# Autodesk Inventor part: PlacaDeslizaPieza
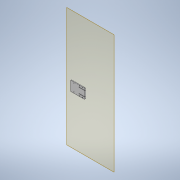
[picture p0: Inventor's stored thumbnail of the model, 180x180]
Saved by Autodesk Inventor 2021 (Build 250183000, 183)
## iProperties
Created: 2021-02
Part Number: PlacaDeslizaPieza
Material: Genérico
Document SubType Name: Modeling
Designer: ATOUZA
Density: 1 g/cm^3
Appearance: Valor por defecto
Author: ATOUZA
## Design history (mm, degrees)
node "Plano de trabajo1"
sketch "Boceto1"
  geometry: L1 (16.874, 259.805)-(-25.126, 259.805) reference; L2 (-25.126, 192.305)-(16.874, 192.305) reference; L3 (-67.126, 243.805)-(-67.126, 208.805) reference; L4 (16.874, 259.805)-(-83.126, 259.805); L5 (-83.126, 259.805)-(-83.126, 191.805); L6 (-83.126, 191.805)-(16.874, 191.805); L7 (16.874, 191.805)-(16.874, 259.805); L8 (-24.376, 246.905)-(-24.376, 206.805) reference; L9 (-24.376, 206.805)-(15.724, 206.805) reference; L10 (15.724, 206.805)-(15.724, 246.905) reference; L11 (15.724, 246.905)-(-24.376, 246.905) reference; L12 (14.224, 245.405)-(14.224, 208.305) reference; L13 (14.224, 208.305)-(-22.876, 208.305) reference; L14 (-22.876, 208.305)-(-22.876, 245.405) reference; L15 (-22.876, 245.405)-(14.224, 245.405) reference; L16 (15.724, 246.905)-(-24.376, 246.905); L17 (-24.376, 246.905)-(-24.376, 245.405); L18 (-24.376, 245.405)-(15.724, 245.405); L19 (15.724, 245.405)-(15.724, 246.905); L20 (15.724, 206.805)-(-24.376, 206.805); L21 (-24.376, 206.805)-(-24.376, 208.305); L22 (-24.376, 208.305)-(15.724, 208.305); L23 (15.724, 208.305)-(15.724, 206.805); L24 (15.824, 245.305)-(-24.476, 245.305); L25 (-24.476, 245.305)-(-24.476, 247.005); L26 (-24.476, 247.005)-(15.824, 247.005); L27 (15.824, 247.005)-(15.824, 245.305); L28 (15.824, 208.405)-(-24.476, 208.405); L29 (-24.476, 208.405)-(-24.476, 206.705); L30 (-24.476, 206.705)-(15.824, 206.705); L31 (15.824, 206.705)-(15.824, 208.405); C1 r 2.5 at (0.374, 256.199) reference; C2 r 2.5 at (-19.626, 256.199) reference; C3 r 2.5 at (-19.626, 196.305) reference; C4 r 2.5 at (0.374, 196.305) reference; C5 r 2.5 at (0.374, 256.199); C6 r 2.5 at (-19.626, 256.199); C7 r 2.5 at (0.374, 196.305); C8 r 2.5 at (-19.626, 196.305); C9 r 2 at (-59.626, 252.555) reference; C10 r 2 at (-59.626, 200.055) reference; C11 r 2 at (-59.626, 252.555); C12 r 2 at (-59.626, 200.055); 1 further point
  constraints: 40 end point, 10 parallel, 6 centre point, 6 coincident, 6 concentric, 5 perpendicular, 4 point on line, 3 horizontal, 6 other
  dimensions: "d0" = 100 distance of L6.end L5.end; "d4" = 0.1 distance between parallel lines of L18 L24; "d5" = 0.1 distance between parallel lines of L22 L28
extrude "Extrusión1" new body sketch "Boceto1" distance "d1" = 5; taper "d2" = 0 deg
fillet "Empalme1" dims "d3" = 4
node "Sólido1"
node "Referencia1"
node "Referencia2"
node "Referencia3"
node "Referencia4"
node "Referencia5"
node "Referencia6"
node "Referencia7"
node "Referencia8"
node "Referencia9"
node "Referencia10"
